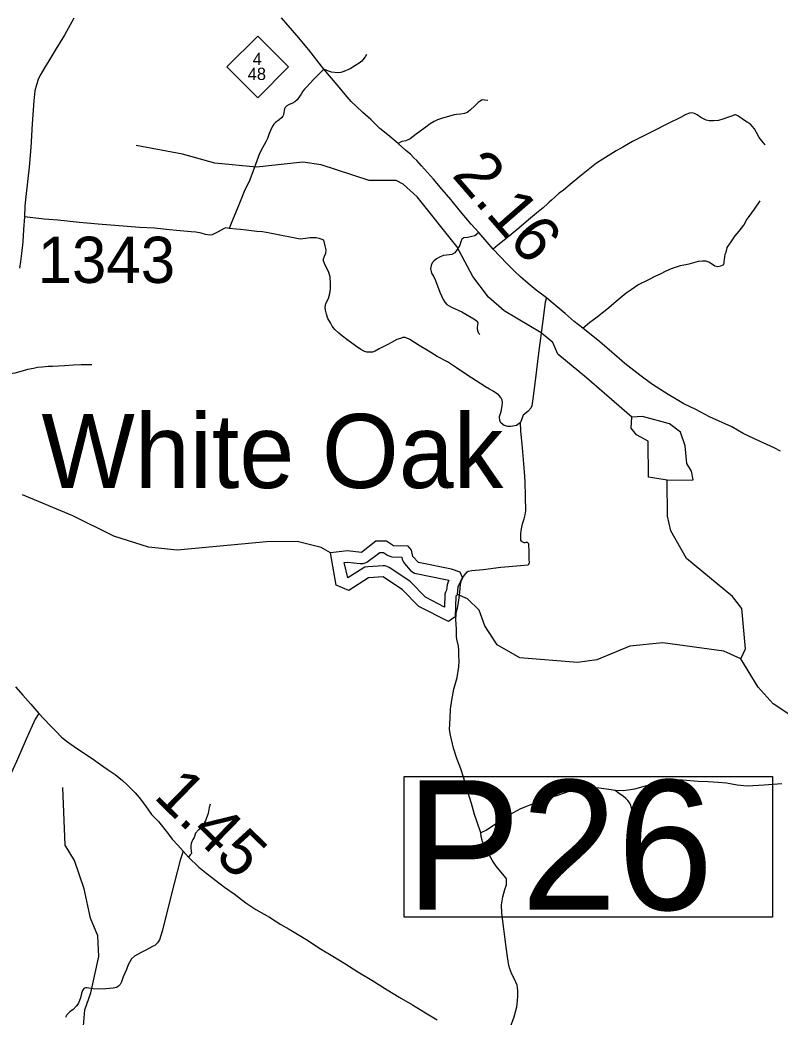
# Model space of a CAD drawing. Extents: x 2290615 to 2522933, y 819489 to 1012715.
# Drawn here: x 2338131 to 2346350, y 883997 to 894770 of the extents above; entities that cross this region are included whole.
import ezdxf

# ---------------------------------------------------------------- set-up
doc = ezdxf.new("R2010")
doc.units = 0
for name, color, linetype in [('Exist Civil Demographics Community Label', 7, 'Continuous'), ('Exist Hydrographic Buffer Line', 7, 'Continuous'), ('Exist Hydrographic Creek Single Shore', 7, 'Continuous'), ('Exist Hydrographic Lake Shore', 7, 'Continuous'), ('Exist Hydrographic Misc Water Feature', 7, 'Continuous'), ('Exist Road Non-System Type 51', 7, 'Continuous'), ('Exist Road Primary NC Attributed', 7, 'Continuous'), ('Exist Road Primary NC Mileage Hundredths English Label', 7, 'Continuous'), ('Exist Road Primary NC Shield CELL', 7, 'Continuous'), ('Exist Road Primary NC Shield Number Label', 7, 'Continuous'), ('Exist Road Primary NC Structure Pipe Number Label', 7, 'Continuous'), ('Exist Road Secondary Mileage Hundredths English Label', 7, 'Continuous'), ('Exist Road Secondary Type 51 Attributed', 7, 'Continuous'), ('Exist Road Secondary Type 51 Number Label', 7, 'Continuous')]:
    doc.layers.add(name, color=color, linetype=linetype)

msp = doc.modelspace()

# ---------------------------------------------------------------- linework, layer by layer
at = {"layer": 'Exist Hydrographic Buffer Line'}
msp.add_lwpolyline([(2342722, 888427), (2342518, 888532), (2342354, 888698), (2342335, 888714), (2342125, 888854), (2342100, 888866), (2342080, 888872), (2342059, 888873), (2341893, 888863), (2341860, 888856), (2341841, 888848), (2341675, 888742), (2341636, 888908), (2341672, 888912), (2341810, 888897), (2341844, 888898), (2341864, 888903), (2341883, 888912), (2342021, 889018), (2342061, 889018), (2342107, 888989), (2342131, 888977), (2342151, 888971), (2342259, 888966), (2342264, 888944), (2342277, 888913), (2342289, 888896), (2342350, 888827), (2342380, 888803), (2342399, 888794), (2342770, 888719), (2342760, 888698), (2342750, 888666), (2342745, 888611), (2342732, 888587), (2342727, 888567), (2342722, 888427)], dxfattribs=at)
at = {"layer": 'Exist Hydrographic Creek Single Shore'}
for points in [[(2341489, 889012), (2341389, 889071), (2341130, 889135), (2340796, 889132), (2339831, 889043), (2339523, 889073), (2339146, 889192), (2338702, 889413), (2338158, 889641)], [(2345927, 887868), (2345742, 887949), (2345083, 888040), (2344725, 888003), (2344369, 887857), (2344161, 887829), (2343536, 887878), (2343292, 888019), (2343157, 888224), (2343096, 888392), (2342970, 888515), (2342861, 888563)], [(2347037, 886965), (2347020, 886997), (2346660, 887127), (2346274, 887380), (2346114, 887561), (2345927, 887868)], [(2338818, 883901), (2338833, 884075), (2338897, 884258), (2338984, 884653), (2338973, 884875), (2338896, 885066), (2338826, 885381), (2338722, 885689), (2338620, 885855), (2338596, 886478)]]:
    msp.add_lwpolyline(points, dxfattribs=at)
at = {"layer": 'Exist Hydrographic Lake Shore'}
for points in [[(2342861, 888563), (2342868, 888645), (2342917, 888746), (2342891, 888804), (2342799, 888836), (2342440, 888907), (2342381, 888973), (2342364, 889042), (2342330, 889083), (2342172, 889090), (2342096, 889139), (2341979, 889137), (2341823, 889016), (2341672, 889033), (2341489, 889012)], [(2342861, 888563), (2342845, 888546), (2342839, 888323), (2342765, 888270), (2342446, 888434), (2342269, 888614), (2342059, 888753), (2341901, 888744), (2341686, 888607), (2341552, 888664), (2341489, 889012)]]:
    msp.add_lwpolyline(points, dxfattribs=at)
at = {"layer": 'Exist Hydrographic Misc Water Feature'}
for points in [[(2344746, 890478), (2344257, 890905), (2343946, 891158), (2343895, 891284), (2343768, 891390), (2343366, 891626), (2343197, 891774), (2343028, 891997), (2342857, 892321), (2342426, 892858), (2342275, 892996), (2342199, 893036), (2341908, 893034), (2341389, 893203), (2341189, 893234), (2340689, 893178), (2340239, 893222), (2339888, 893319), (2339387, 893413)], [(2345129, 889798), (2344928, 889829), (2344924, 890220), (2344798, 890287), (2344739, 890360), (2344746, 890478)], [(2345129, 889798), (2345412, 889803), (2345394, 889895), (2345343, 889978), (2345324, 890167), (2345273, 890316), (2345155, 890407), (2344862, 890487), (2344746, 890478)], [(2345927, 887868), (2345975, 887975), (2345937, 888410), (2345835, 888541), (2345339, 888950), (2345169, 889249), (2345133, 889408), (2345129, 889798)]]:
    msp.add_lwpolyline(points, dxfattribs=at)
at = {"layer": 'Exist Road Non-System Type 51'}
for points in [[(2341878, 894397), (2341864, 894373), (2341849, 894353), (2341829, 894326), (2341799, 894304), (2341751, 894273), (2341702, 894243), (2341634, 894214), (2341600, 894202), (2341570, 894199), (2341500, 894207), (2341448, 894222), (2341418, 894238), (2341358, 894182), (2341306, 894127), (2341268, 894087), (2341231, 894044), (2341209, 894021), (2341192, 894000), (2341171, 893967), (2341153, 893943), (2341130, 893908), (2341104, 893886), (2341079, 893872), (2341055, 893861), (2341041, 893856), (2341019, 893841), (2341009, 893833), (2341000, 893824), (2340993, 893810), (2340987, 893791), (2340984, 893770), (2340981, 893744), (2340974, 893730), (2340959, 893713), (2340933, 893692), (2340895, 893662), (2340876, 893644), (2340865, 893627), (2340847, 893593), (2340824, 893531), (2340807, 893489), (2340790, 893453), (2340755, 893389), (2340722, 893328), (2340692, 893246), (2340655, 893139), (2340616, 893042), (2340557, 892917), (2340490, 892756), (2340431, 892607), (2340392, 892515)], [(2343191, 893901), (2343155, 893904), (2343134, 893907), (2343121, 893904), (2343106, 893894), (2343085, 893878), (2343054, 893847), (2343000, 893794), (2342966, 893769), (2342939, 893758), (2342898, 893751), (2342852, 893747), (2342826, 893743), (2342689, 893705), (2342645, 893689), (2342611, 893674), (2342568, 893646), (2342519, 893611), (2342468, 893574), (2342417, 893536), (2342352, 893487), (2342303, 893463), (2342259, 893455), (2342221, 893435)], [(2346189, 893421), (2346153, 893463), (2346124, 893500), (2346094, 893553), (2346073, 893593), (2346050, 893623), (2346026, 893647), (2345994, 893667), (2345956, 893690), (2345917, 893718), (2345895, 893734), (2345879, 893742), (2345867, 893744), (2345857, 893743), (2345836, 893735), (2345793, 893718), (2345730, 893697), (2345685, 893683), (2345630, 893680), (2345582, 893680), (2345552, 893688), (2345494, 893716), (2345453, 893744), (2345426, 893758), (2345397, 893766), (2345372, 893764), (2345333, 893749), (2345273, 893714), (2345140, 893650), (2344980, 893569), (2344820, 893490), (2344755, 893457), (2344652, 893394), (2344577, 893354), (2344435, 893266), (2344367, 893224), (2344185, 893080), (2344079, 892991), (2344007, 892931), (2343963, 892897), (2343918, 892857), (2343879, 892821), (2343854, 892802), (2343839, 892787), (2343788, 892741), (2343715, 892681), (2343631, 892611), (2343526, 892521), (2343442, 892450), (2343367, 892390), (2343297, 892337), (2343249, 892295)], [(2344218, 891439), (2344293, 891504), (2344358, 891553), (2344476, 891646), (2344598, 891748), (2344685, 891821), (2344742, 891859), (2344811, 891908), (2344931, 891966), (2345007, 892004), (2345056, 892028), (2345119, 892058), (2345177, 892083), (2345219, 892100), (2345274, 892116), (2345369, 892135), (2345467, 892163), (2345511, 892169), (2345543, 892166), (2345589, 892153), (2345645, 892112), (2345678, 892105), (2345711, 892112), (2345728, 892120), (2345741, 892127), (2345746, 892144), (2345746, 892160), (2345750, 892183), (2345754, 892210), (2345758, 892238), (2345766, 892262), (2345775, 892293), (2345780, 892310), (2345796, 892335), (2345821, 892371), (2345865, 892437), (2345909, 892489), (2345959, 892552), (2345972, 892579), (2345983, 892602), (2346015, 892646), (2346075, 892725), (2346135, 892814)], [(2340392, 892515), (2340356, 892522), (2340340, 892518), (2340274, 892482), (2340247, 892465), (2340210, 892449), (2340184, 892446), (2340137, 892452), (2340091, 892465), (2340032, 892476), (2339984, 892479), (2339905, 892489), (2339823, 892494), (2339747, 892503), (2339586, 892519), (2339426, 892526), (2339291, 892538), (2338978, 892563), (2338777, 892583), (2338542, 892608), (2338395, 892619), (2338180, 892641)], [(2343543, 890420), (2343499, 890389), (2343438, 890377), (2343406, 890377), (2343367, 890390), (2343334, 890412), (2343320, 890439), (2343318, 890484), (2343334, 890539), (2343346, 890600), (2343348, 890635), (2343346, 890663), (2343332, 890690), (2343306, 890719), (2343247, 890758), (2343208, 890782), (2343167, 890805), (2343066, 890870), (2342965, 890936), (2342850, 891011), (2342753, 891076), (2342641, 891132), (2342544, 891195), (2342449, 891254), (2342346, 891318), (2342309, 891336), (2342295, 891339), (2342270, 891338), (2342245, 891330), (2342205, 891316), (2342149, 891284), (2342108, 891262), (2342016, 891216), (2341973, 891193), (2341943, 891182), (2341910, 891179), (2341899, 891179), (2341882, 891181), (2341850, 891193), (2341818, 891210), (2341758, 891249), (2341667, 891319), (2341620, 891354), (2341581, 891385), (2341536, 891426), (2341508, 891463), (2341489, 891498), (2341461, 891545), (2341446, 891591), (2341434, 891635), (2341433, 891668), (2341440, 891706), (2341466, 891760), (2341482, 891815), (2341489, 891866), (2341491, 891919), (2341486, 891995), (2341473, 892042), (2341423, 892140), (2341414, 892168), (2341415, 892190), (2341425, 892219), (2341438, 892250), (2341442, 892286), (2341433, 892328), (2341416, 892390), (2341388, 892403), (2341367, 892408), (2341336, 892415), (2341311, 892415), (2341270, 892415), (2341218, 892408), (2341160, 892402), (2340833, 892466), (2340755, 892479), (2340693, 892485), (2340579, 892499), (2340518, 892504), (2340471, 892508), (2340392, 892515)], [(2343094, 892473), (2343050, 892439), (2343016, 892430), (2342976, 892421), (2342931, 892415), (2342908, 892401), (2342898, 892372), (2342886, 892335), (2342860, 892289), (2342833, 892255), (2342802, 892235), (2342776, 892231), (2342712, 892224), (2342676, 892212), (2342636, 892190), (2342605, 892165), (2342587, 892145), (2342577, 892116), (2342572, 892085), (2342583, 892035), (2342603, 892001), (2342623, 891955), (2342671, 891827), (2342709, 891750), (2342724, 891721), (2342746, 891697), (2342799, 891665), (2342908, 891615), (2343040, 891541), (2343066, 891524), (2343072, 891517), (2343078, 891505), (2343081, 891493), (2343079, 891471), (2343077, 891451), (2343077, 891432), (2343080, 891416), (2343086, 891397), (2343091, 891387), (2343104, 891373)], [(2343825, 891767), (2343811, 891719), (2343785, 891523), (2343739, 891168), (2343707, 890898), (2343678, 890676), (2343668, 890602), (2343657, 890574), (2343622, 890541), (2343572, 890499), (2343557, 890462), (2343543, 890420)], [(2343825, 891767), (2343811, 891719), (2343785, 891523), (2343739, 891168), (2343707, 890898), (2343678, 890676), (2343668, 890602), (2343657, 890574), (2343622, 890541), (2343572, 890499), (2343557, 890462), (2343543, 890420)], [(2337713, 890950), (2337731, 890941), (2337742, 890938), (2337759, 890938), (2337834, 890939), (2337990, 890948), (2338079, 890957), (2338159, 890980), (2338216, 890998), (2338277, 891006), (2338320, 891018), (2338372, 891022), (2338438, 891028), (2338485, 891028), (2338614, 891035), (2338710, 891042), (2338795, 891047), (2338909, 891049)], [(2343114, 885989), (2343077, 886102), (2343048, 886185), (2343013, 886303), (2342974, 886432), (2342931, 886580), (2342897, 886679), (2342857, 886789), (2342819, 886902), (2342786, 887044), (2342777, 887103), (2342784, 887228), (2342787, 887322), (2342802, 887421), (2342823, 887541), (2342859, 887667), (2342878, 887782), (2342880, 887846), (2342878, 887905), (2342877, 887957), (2342874, 888004), (2342854, 888079), (2342851, 888112), (2342850, 888159), (2342851, 888189), (2342847, 888242), (2342845, 888289), (2342848, 888356), (2342866, 888434), (2342879, 888526), (2342887, 888586), (2342895, 888672), (2342905, 888719), (2342929, 888758), (2342954, 888789), (2342966, 888807), (2342979, 888816), (2343016, 888822), (2343140, 888832), (2343332, 888856), (2343543, 888875), (2343625, 888883), (2343635, 888891), (2343640, 888909), (2343637, 888945), (2343637, 889000), (2343637, 889049), (2343635, 889086), (2343635, 889097), (2343633, 889108), (2343630, 889114), (2343626, 889118), (2343619, 889123), (2343614, 889123), (2343603, 889123), (2343591, 889122), (2343582, 889121), (2343575, 889124), (2343563, 889132), (2343555, 889140), (2343549, 889148), (2343546, 889156), (2343546, 889164), (2343547, 889186), (2343549, 889215), (2343552, 889251), (2343559, 889289), (2343567, 889325), (2343583, 889381), (2343594, 889422), (2343600, 889466), (2343598, 889620), (2343595, 889781), (2343588, 889887), (2343576, 890019), (2343565, 890146), (2343546, 890330), (2343543, 890420)], [(2338337, 887277), (2338297, 887216), (2338198, 887001), (2338093, 886760), (2338015, 886586)], [(2344567, 886444), (2344523, 886453), (2344396, 886470), (2344247, 886473), (2344165, 886461), (2344077, 886437), (2343953, 886395), (2343792, 886344), (2343663, 886295), (2343542, 886247), (2343424, 886182), (2343301, 886101), (2343175, 886015), (2343114, 885989)], [(2344567, 886444), (2344523, 886453), (2344396, 886470), (2344247, 886473), (2344165, 886461), (2344077, 886437), (2343953, 886395), (2343792, 886344), (2343663, 886295), (2343542, 886247), (2343424, 886182), (2343301, 886101), (2343175, 886015), (2343114, 885989)], [(2346369, 886517), (2346177, 886501), (2345996, 886492), (2345887, 886501), (2345772, 886524), (2345680, 886533), (2345573, 886538), (2345466, 886542), (2345297, 886556), (2345181, 886557), (2345097, 886546), (2345030, 886529), (2344890, 886491), (2344777, 886458), (2344733, 886452), (2344655, 886443), (2344567, 886444)], [(2346369, 886517), (2346177, 886501), (2345996, 886492), (2345887, 886501), (2345772, 886524), (2345680, 886533), (2345573, 886538), (2345466, 886542), (2345297, 886556), (2345181, 886557), (2345097, 886546), (2345030, 886529), (2344890, 886491), (2344777, 886458), (2344733, 886452), (2344655, 886443), (2344567, 886444)], [(2344776, 886014), (2344765, 886046), (2344757, 886080), (2344756, 886156), (2344754, 886198), (2344745, 886258), (2344733, 886292), (2344720, 886318), (2344706, 886337), (2344682, 886359), (2344655, 886385), (2344615, 886410), (2344567, 886444)], [(2344776, 886014), (2344765, 886046), (2344757, 886080), (2344756, 886156), (2344754, 886198), (2344745, 886258), (2344733, 886292), (2344720, 886318), (2344706, 886337), (2344682, 886359), (2344655, 886385), (2344615, 886410), (2344567, 886444)], [(2340188, 886297), (2340178, 886261), (2340165, 886195), (2340150, 886151), (2340138, 886117), (2340112, 886078), (2340061, 886020), (2340030, 885985), (2340017, 885936), (2340001, 885916), (2339993, 885900), (2339982, 885872), (2339980, 885843), (2339981, 885822), (2339983, 885791), (2339985, 885766), (2339973, 885749), (2339955, 885726)], [(2343437, 883891), (2343475, 883999), (2343503, 884107), (2343512, 884172), (2343515, 884228), (2343516, 884281), (2343512, 884313), (2343508, 884343), (2343479, 884405), (2343451, 884460), (2343428, 884519), (2343418, 884553), (2343404, 884649), (2343390, 884754), (2343343, 885120), (2343339, 885210), (2343351, 885296), (2343375, 885376), (2343392, 885425), (2343394, 885439), (2343393, 885471), (2343391, 885489), (2343385, 885502), (2343279, 885629), (2343239, 885693), (2343194, 885771), (2343158, 885845), (2343138, 885884), (2343131, 885900), (2343129, 885908), (2343126, 885918), (2343121, 885939), (2343120, 885947), (2343114, 885989)], [(2339897, 885788), (2339863, 885693), (2339800, 885441), (2339729, 885171), (2339672, 884937), (2339639, 884832), (2339620, 884801), (2339591, 884771), (2339571, 884762), (2339484, 884718), (2339441, 884695), (2339370, 884654), (2339338, 884625), (2339320, 884594), (2339303, 884562), (2339284, 884511), (2339249, 884432), (2339241, 884412), (2339230, 884378), (2339214, 884350), (2339196, 884330), (2339174, 884318), (2339140, 884311), (2339061, 884302), (2338983, 884297), (2338923, 884301), (2338856, 884312), (2338839, 884312), (2338823, 884306), (2338809, 884286), (2338796, 884252), (2338787, 884206), (2338776, 884177), (2338760, 884141), (2338740, 884114), (2338707, 884080), (2338671, 884055), (2338638, 884021), (2338624, 883994)]]:
    msp.add_lwpolyline(points, dxfattribs=at)
at = {"layer": 'Exist Road Primary NC Attributed'}
msp.add_lwpolyline([(2346356, 890112), (2346286, 890147), (2346129, 890219), (2345952, 890303), (2345827, 890374), (2345589, 890482), (2345438, 890562), (2345311, 890622), (2345219, 890678), (2345139, 890722), (2345062, 890772), (2344960, 890840), (2344833, 890931), (2344671, 891059), (2344532, 891179), (2344402, 891292), (2344218, 891439), (2344125, 891513), (2344025, 891599), (2343898, 891706), (2343825, 891767), (2343712, 891850), (2343625, 891921), (2343544, 891996), (2343479, 892056), (2343397, 892137), (2343249, 892295), (2343094, 892473), (2343010, 892563), (2342895, 892702), (2342792, 892830), (2342698, 892938), (2342604, 893050), (2342474, 893195), (2342423, 893252), (2342391, 893281), (2342353, 893318), (2342305, 893359), (2342221, 893435), (2342108, 893528), (2342024, 893597), (2341924, 893694), (2341838, 893770), (2341769, 893835), (2341713, 893887), (2341648, 893965), (2341582, 894045), (2341418, 894238), (2341256, 894448), (2341126, 894601), (2340959, 894793)], dxfattribs=at)
at = {"layer": 'Exist Road Primary NC Shield CELL'}
msp.add_lwpolyline([(2340370, 894263), (2340703, 894596), (2341036, 894263), (2340703, 893930)], close=True, dxfattribs=at)
at = {"layer": 'Exist Road Primary NC Structure Pipe Number Label'}
msp.add_lwpolyline([(2342286, 886596), (2346268, 886596), (2346268, 885077), (2342286, 885077)], close=True, dxfattribs=at)
at = {"layer": 'Exist Road Secondary Type 51 Attributed'}
for points in [[(2338714, 894788), (2338612, 894606), (2338519, 894454), (2338443, 894329), (2338397, 894251), (2338356, 894185), (2338333, 894137), (2338310, 894067), (2338293, 894003), (2338282, 893896), (2338262, 893646), (2338248, 893393), (2338230, 893181), (2338200, 892894), (2338185, 892762), (2338180, 892641), (2338170, 892504), (2338161, 892374), (2338150, 892247), (2338138, 892161), (2338126, 892088)], [(2338083, 887564), (2338162, 887475), (2338251, 887376), (2338337, 887277), (2338456, 887150), (2338523, 887083), (2338582, 887022), (2338646, 886971), (2338717, 886919), (2338807, 886858), (2338914, 886790), (2339003, 886727), (2339074, 886674), (2339160, 886617), (2339241, 886552), (2339292, 886506), (2339342, 886457), (2339377, 886419), (2339419, 886370), (2339488, 886281), (2339553, 886187), (2339631, 886111), (2339727, 885987), (2339779, 885921), (2339838, 885854), (2339897, 885788), (2339955, 885726), (2340066, 885618), (2340156, 885543), (2340250, 885471), (2340344, 885402), (2340446, 885327), (2340574, 885231), (2340683, 885159), (2340829, 885078), (2340953, 884999), (2341042, 884946), (2341221, 884838), (2341381, 884736), (2341516, 884654), (2341646, 884575), (2341785, 884487), (2341936, 884397), (2342101, 884293), (2342232, 884214), (2342375, 884128), (2342516, 884042), (2342641, 883967)]]:
    msp.add_lwpolyline(points, dxfattribs=at)

# ---------------------------------------------------------------- texts
at = {"layer": 'Exist Civil Demographics Community Label'}
msp.add_text('White Oak', height=800, rotation=360, dxfattribs=at).set_placement((2338364, 889713))
at = {"layer": 'Exist Road Primary NC Mileage Hundredths English Label'}
msp.add_text('2.16', height=500, rotation=310.9993, dxfattribs=at).set_placement((2342792, 893088))
at = {"layer": 'Exist Road Primary NC Shield Number Label'}
for s, height, p in [('4', 132, (2340649, 894283)), ('48', 132.5, (2340595, 894121))]:
    msp.add_text(s, height=height, dxfattribs=at).set_placement(p)
at = {"layer": 'Exist Road Primary NC Structure Pipe Number Label'}
msp.add_text('P26', height=1400, dxfattribs=at).set_placement((2342299, 885156))
at = {"layer": 'Exist Road Secondary Mileage Hundredths English Label'}
msp.add_text('1.45', height=500, rotation=315.6804, dxfattribs=at).set_placement((2339565, 886372))
at = {"layer": 'Exist Road Secondary Type 51 Number Label'}
msp.add_text('1343', height=500, rotation=360, dxfattribs=at).set_placement((2338322, 891928))

doc.saveas('drawing.dxf')
